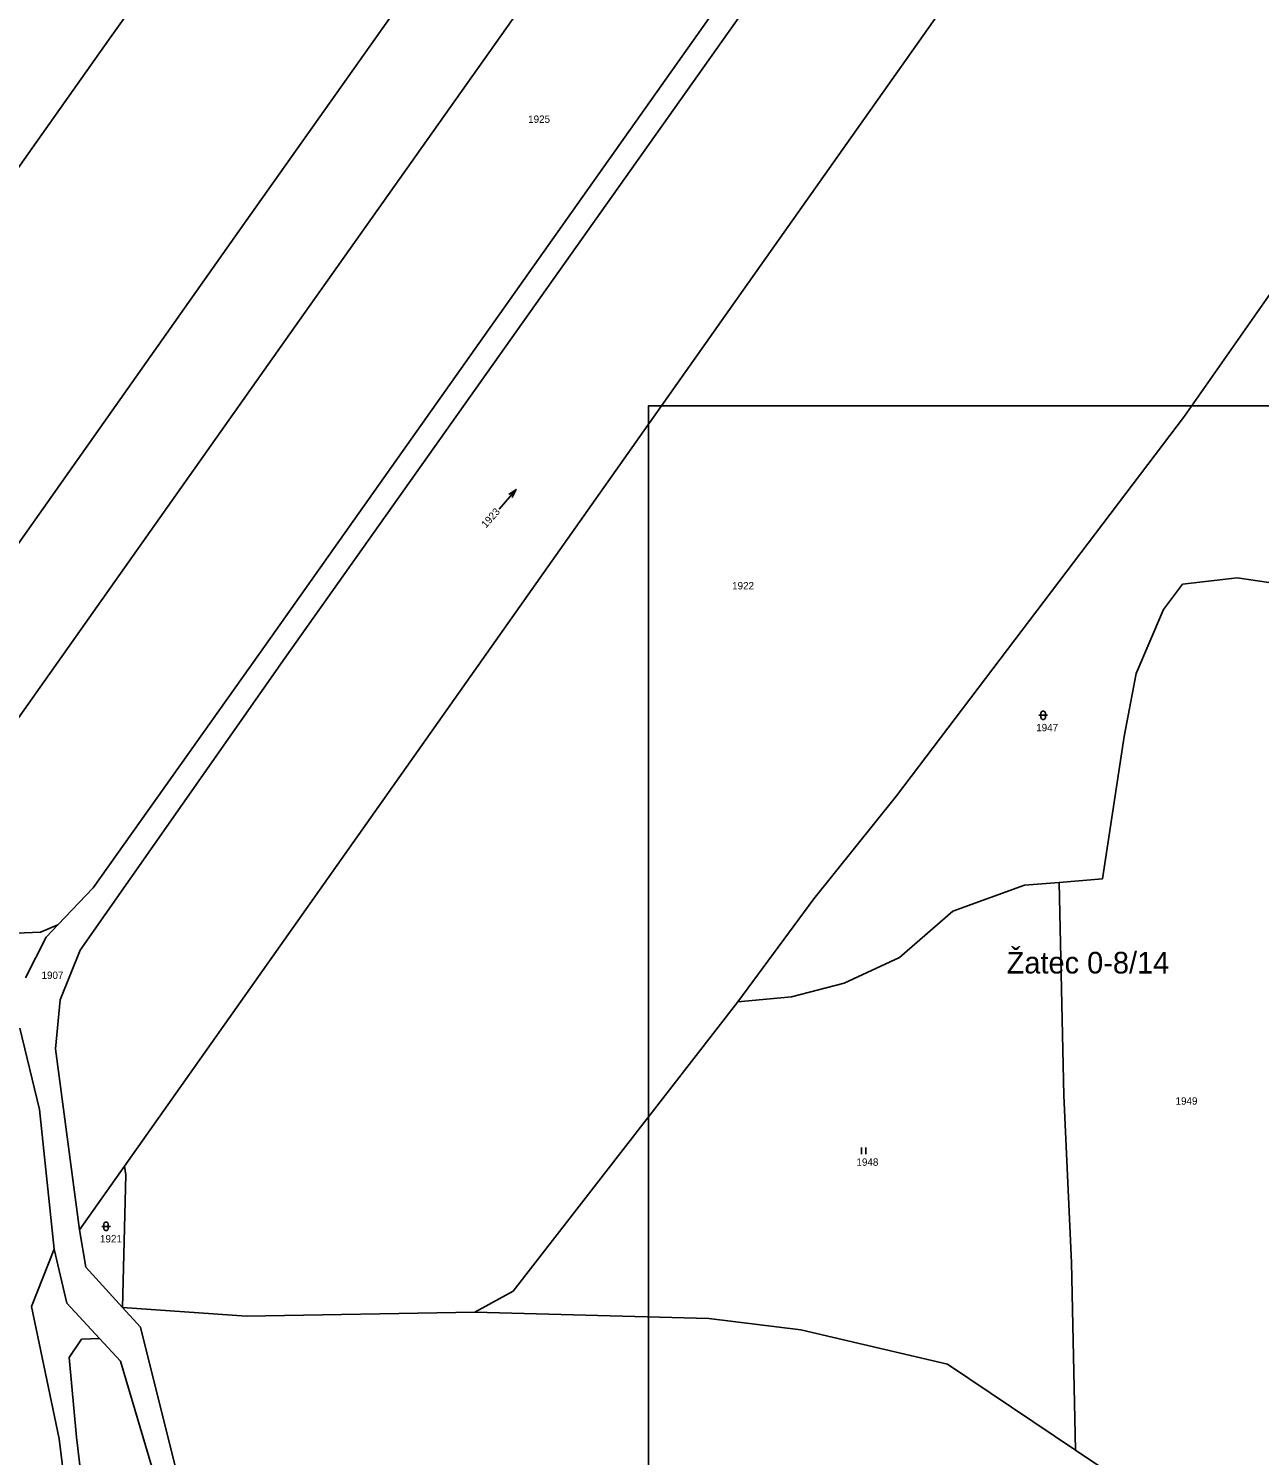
# Model space of a CAD drawing. Extents: x -801853 to -800578, y -1017479 to -1016338.
# Drawn here: x -801702.3 to -801418.1, y -1016987.3 to -1016658 of the extents above; entities that cross this region are included whole.
import ezdxf

# ---------------------------------------------------------------- set-up
doc = ezdxf.new("R2010")
doc.units = 0
for name, color, linetype in [('Default', 7, 'Continuous'), ('KLADY_ZMVM', 7, 'Continuous'), ('KN_HRANICE', 7, 'Continuous'), ('KN_KULTURY', 7, 'Continuous'), ('KN_PARCELY', 7, 'Continuous'), ('LEGENDA', 7, 'Continuous')]:
    doc.layers.add(name, color=color, linetype=linetype)

# ---------------------------------------------------------------- blocks, each defined once
blk = doc.blocks.new('306')
at = {"layer": 'Default'}
for p, q in [((-0.5, 1.5), (-0.5, 0)), ((0.5, 0), (0.5, 1.5))]:
    blk.add_line(p, q, dxfattribs=at)
blk = doc.blocks.new('316')
at = {"layer": 'Default'}
for points in [[(-1, 1), (0.27, 1), (1, 1)], [(-0.5, 1.5), (-0.4, 1.79), (-0.15, 1.97), (0.16, 1.97), (0.41, 1.79), (0.51, 1.5), (0.51, 0.5), (0.41, 0.21), (0.16, 0.03), (-0.15, 0.03), (-0.4, 0.21), (-0.5, 0.5), (-0.5, 1.5)]]:
    blk.add_lwpolyline(points, dxfattribs=at)
blk = doc.blocks.new('802')
at = {"layer": 'Default'}
blk.add_line((-3, 0), (3, 0), dxfattribs=at)
blk.add_lwpolyline([(1, 0.5), (3, 0), (1, -0.5)], dxfattribs=at)

msp = doc.modelspace()

# ---------------------------------------------------------------- linework, layer by layer
at = {"layer": 'KN_HRANICE'}
for p, q in [((-801683.77, -1016660.64), (-801596.87, -1016538.03)), ((-801653.68, -1016704.77), (-801566.87, -1016582.04)), ((-801447.6, -1016591.37), (-801541.38, -1016724.15)), ((-801639.69, -1016725.29), (-801552.88, -1016602.56)), ((-801575.59, -1016698.58), (-801517.05, -1016615.83)), ((-801571.59, -1016702.44), (-801511.85, -1016618.06)), ((-801760.35, -1016768.65), (-801683.77, -1016660.64)), ((-801647.38, -1016800.06), (-801575.59, -1016698.58)), ((-801643.1, -1016803.32), (-801571.59, -1016702.44)), ((-801734.03, -1016818.37), (-801653.68, -1016704.77)), ((-801435.35, -1016747.43), (-801414.37, -1016717.41)), ((-801721.83, -1016841.42), (-801639.69, -1016725.29)), ((-801541.38, -1016724.15), (-801613.25, -1016825.92)), ((-801435.35, -1016747.43), (-801501.91, -1016835.06)), ((-801435.81, -1016786.18), (-801423.24, -1016784.75)), ((-801423.24, -1016784.75), (-801409.24, -1016786.85)), ((-801440.23, -1016792.04), (-801435.81, -1016786.18)), ((-801446.53, -1016806.87), (-801440.23, -1016792.04)), ((-801687.33, -1016856.32), (-801647.38, -1016800.06)), ((-801690.36, -1016870.7), (-801643.1, -1016803.32)), ((-801449.28, -1016821.35), (-801446.53, -1016806.87)), ((-801454.35, -1016854.21), (-801449.28, -1016821.35)), ((-801613.25, -1016825.92), (-801680.1, -1016920.57)), ((-801501.91, -1016835.06), (-801520.97, -1016858.87)), ((-801695.48, -1016864.85), (-801687.33, -1016856.32)), ((-801488.84, -1016861.66), (-801472.31, -1016855.72)), ((-801472.31, -1016855.72), (-801464.32, -1016855.05)), ((-801464.32, -1016855.05), (-801454.35, -1016854.21)), ((-801464.32, -1016855.05), (-801463.26, -1016904.2)), ((-801520.97, -1016858.87), (-801538.54, -1016882.63)), ((-801501.16, -1016872.36), (-801488.84, -1016861.66)), ((-801705.06, -1016866.78), (-801699.53, -1016866.51)), ((-801695.48, -1016864.85), (-801699.53, -1016866.51)), ((-801698.22, -1016867.71), (-801695.48, -1016864.85)), ((-801702.94, -1016877.09), (-801698.22, -1016867.71)), ((-801694.95, -1016882.15), (-801690.36, -1016870.7)), ((-801513.97, -1016878.29), (-801501.16, -1016872.36)), ((-801526.09, -1016881.45), (-801513.97, -1016878.29)), ((-801696.06, -1016893.49), (-801694.95, -1016882.15)), ((-801590.36, -1016949.37), (-801538.54, -1016882.63)), ((-801538.54, -1016882.63), (-801526.09, -1016881.45)), ((-801699.73, -1016907.45), (-801704.27, -1016888.67)), ((-801690.47, -1016935.25), (-801696.06, -1016893.49)), ((-801463.26, -1016904.2), (-801461.44, -1016942.77)), ((-801696.36, -1016939.74), (-801699.73, -1016907.45)), ((-801680.1, -1016920.57), (-801690.47, -1016935.25)), ((-801680.56, -1016953.19), (-801679.8, -1016922.57)), ((-801679.8, -1016922.57), (-801680.1, -1016920.57)), ((-801689.06, -1016943.83), (-801690.47, -1016935.25)), ((-801696.36, -1016939.74), (-801701.6, -1016952.9)), ((-801693.42, -1016952.2), (-801696.36, -1016939.74)), ((-801461.44, -1016942.77), (-801460.58, -1016986.09)), ((-801680.56, -1016953.19), (-801689.06, -1016943.83)), ((-801599.25, -1016954.23), (-801590.36, -1016949.37)), ((-801701.6, -1016952.9), (-801695.19, -1016983.45)), ((-801685.92, -1016960.3), (-801693.42, -1016952.2)), ((-801676.44, -1016957.72), (-801680.56, -1016953.19)), ((-801680.56, -1016953.19), (-801651.92, -1016955.2)), ((-801651.92, -1016955.2), (-801599.25, -1016954.23)), ((-801545.22, -1016955.68), (-801599.25, -1016954.23)), ((-801523.93, -1016958.35), (-801545.22, -1016955.68)), ((-801661.3, -1017018.39), (-801676.44, -1016957.72)), ((-801490.1, -1016966.21), (-801523.93, -1016958.35)), ((-801692.86, -1016964.69), (-801690.07, -1016960.49)), ((-801690.07, -1016960.49), (-801685.92, -1016960.3)), ((-801681.07, -1016965.55), (-801685.92, -1016960.3)), ((-801691.2, -1016983.13), (-801692.86, -1016964.69)), ((-801673.18, -1016992.05), (-801681.07, -1016965.55)), ((-801460.58, -1016986.09), (-801490.1, -1016966.21)), ((-801692.25, -1017007.35), (-801695.19, -1016983.45)), ((-801688.27, -1017006.93), (-801691.2, -1016983.13)), ((-801460.58, -1016986.09), (-801454.5, -1016990.2))]:
    msp.add_line(p, q, dxfattribs=at)
at = {"layer": 'LEGENDA'}
msp.add_lwpolyline([(-801559.16, -1017339.08), (-800718.16, -1017339.08), (-800718.16, -1016745.08), (-801559.16, -1016745.08)], close=True, dxfattribs=at)

# ---------------------------------------------------------------- block references
at = {"layer": 'KN_KULTURY', "rotation": 49.56084899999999}
msp.add_blockref('802', (-801591.64, -1016766.64), dxfattribs=at)
at = {"layer": 'KN_KULTURY'}
for name, p in [('316', (-801468.02, -1016817.47)), ('306', (-801509.47, -1016917.76)), ('316', (-801684.38, -1016935.45))]:
    msp.add_blockref(name, p, dxfattribs=at)

# ---------------------------------------------------------------- texts
at = {"layer": 'KLADY_ZMVM'}
msp.add_text('Žatec 0-8/14', height=5, dxfattribs=at).set_placement((-801476.44, -1016876.08))
at = {"layer": 'KN_PARCELY'}
for s, p in [('1925', (-801586.92, -1016679.74)), ('1922', (-801539.83, -1016787.43)), ('1947', (-801469.62, -1016820.17)), ('1907', (-801699.27, -1016877.33)), ('1949', (-801437.45, -1016906.35)), ('1948', (-801511.12, -1016920.46)), ('1921', (-801685.77, -1016938.15))]:
    msp.add_text(s, height=1.7, dxfattribs=at).set_placement(p)
msp.add_text('1923', height=1.7, rotation=48.472, dxfattribs=at).set_placement((-801596.64, -1016773.36))

doc.saveas('drawing.dxf')
